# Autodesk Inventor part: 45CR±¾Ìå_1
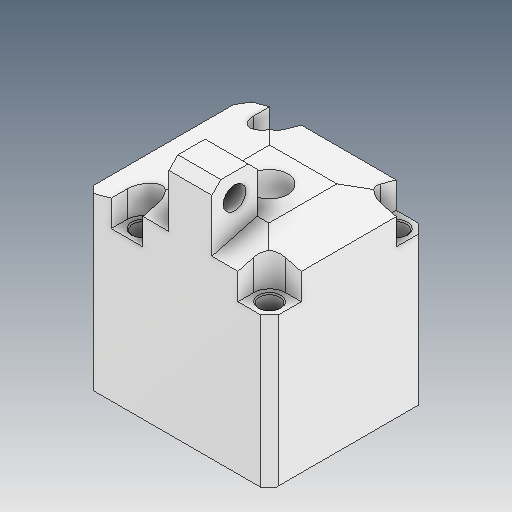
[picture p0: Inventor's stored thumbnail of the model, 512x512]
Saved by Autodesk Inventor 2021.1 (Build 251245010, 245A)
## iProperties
Created: 2021-05
Part Number: 45CR±¾Ìå_1
Material: Ogólny
Document SubType Name: Modeling
Designer: user
Density: 1 g/cm^3
Appearance: Domyślna
Author: user
Revision Number: ÈÎºÎ
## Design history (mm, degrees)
feature "ÇÐ³ý-À­Éì1"
node "Bryła1"
